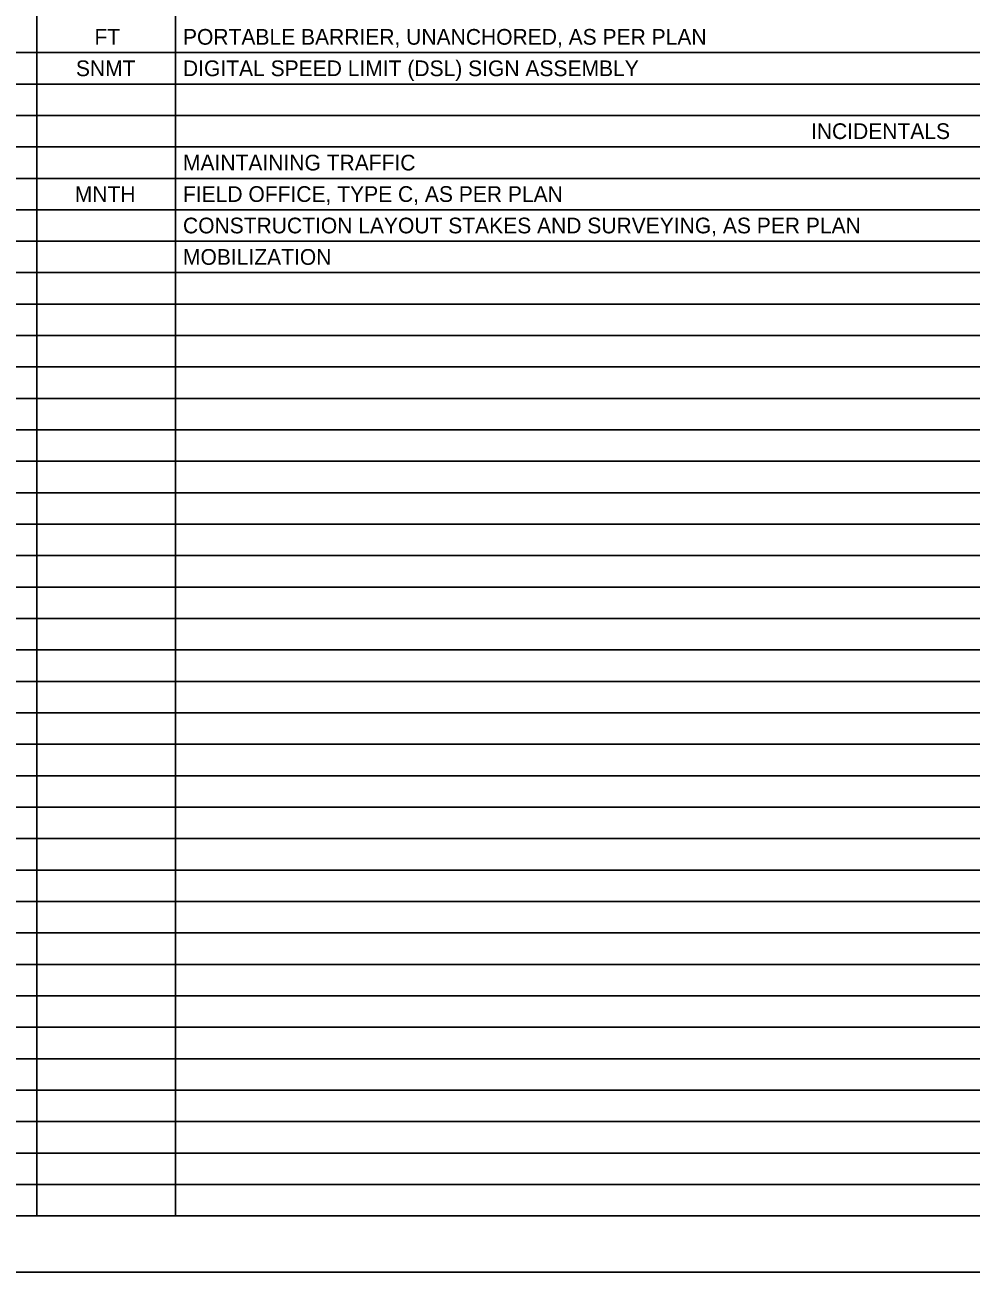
# Model space of a CAD drawing. Extents: x 0 to 34, y 0 to 22.
# Drawn here: x 17.16 to 25.58, y 0 to 11.11 of the extents above; entities that cross this region are included whole.
import ezdxf

# ---------------------------------------------------------------- set-up
doc = ezdxf.new("R2010")
doc.units = 0
for name, color, linetype in [('SH_Border', 7, 'Continuous'), ('SH_Cut_Line', 7, 'Continuous'), ('SH_Data', 7, 'Continuous'), ('SH_Text', 7, 'Continuous')]:
    doc.layers.add(name, color=color, linetype=linetype)

msp = doc.modelspace()

# ---------------------------------------------------------------- linework, layer by layer
at = {"layer": 'SH_Border'}
msp.add_lwpolyline([(1.5, 21.5), (33.5, 21.5), (33.5, 0.5), (1.5, 0.5)], close=True, dxfattribs=at)
at = {"layer": 'SH_Cut_Line'}
msp.add_lwpolyline([(0, 0), (34, 0), (34, 22), (0, 22)], close=True, dxfattribs=at)
at = {"layer": 'SH_Data'}
for p, q in [((17.262, 21.5), (17.262, 0.5)), ((18.498, 21.5), (18.498, 0.5)), ((1.5, 10.86), (32.004, 10.86)), ((1.5, 10.58), (32.004, 10.58)), ((1.5, 10.3), (32.004, 10.3)), ((1.5, 10.02), (32.004, 10.02)), ((1.5, 9.74), (32.004, 9.74)), ((1.5, 9.46), (32.004, 9.46)), ((1.5, 9.18), (32.004, 9.18)), ((1.5, 8.9), (32.004, 8.9)), ((1.5, 8.62), (32.004, 8.62)), ((1.5, 8.34), (32.004, 8.34)), ((1.5, 8.06), (32.004, 8.06)), ((1.5, 7.78), (32.004, 7.78)), ((1.5, 7.5), (32.004, 7.5)), ((1.5, 7.22), (32.004, 7.22)), ((1.5, 6.94), (32.004, 6.94)), ((1.5, 6.66), (32.004, 6.66)), ((1.5, 6.38), (32.004, 6.38)), ((1.5, 6.1), (32.004, 6.1)), ((1.5, 5.82), (32.004, 5.82)), ((1.5, 5.54), (32.004, 5.54)), ((1.5, 5.26), (32.004, 5.26)), ((1.5, 4.98), (32.004, 4.98)), ((1.5, 4.7), (32.004, 4.7)), ((1.5, 4.42), (32.004, 4.42)), ((1.5, 4.14), (32.004, 4.14)), ((1.5, 3.86), (32.004, 3.86)), ((1.5, 3.58), (32.004, 3.58)), ((1.5, 3.3), (32.004, 3.3)), ((1.5, 3.02), (32.004, 3.02)), ((1.5, 2.74), (32.004, 2.74)), ((1.5, 2.46), (32.004, 2.46)), ((1.5, 2.18), (32.004, 2.18)), ((1.5, 1.9), (32.004, 1.9)), ((1.5, 1.62), (32.004, 1.62)), ((1.5, 1.34), (32.004, 1.34)), ((1.5, 1.06), (32.004, 1.06)), ((1.5, 0.78), (32.004, 0.78)), ((1.5, 0.5), (32.004, 0.5))]:
    msp.add_line(p, q, dxfattribs=at)

# ---------------------------------------------------------------- texts
at = {"layer": 'SH_Text'}
for s, p in [('FT', (17.776, 10.93)), ('PORTABLE BARRIER, UNANCHORED, AS PER PLAN', (18.564, 10.93)), ('SNMT', (17.611, 10.65)), ('DIGITAL SPEED LIMIT (DSL) SIGN ASSEMBLY', (18.564, 10.65)), ('INCIDENTALS', (24.154, 10.09)), ('MAINTAINING TRAFFIC', (18.564, 9.81)), ('MNTH', (17.601, 9.53)), ('FIELD OFFICE, TYPE C, AS PER PLAN', (18.564, 9.53)), ('CONSTRUCTION LAYOUT STAKES AND SURVEYING, AS PER PLAN', (18.564, 9.25)), ('MOBILIZATION', (18.564, 8.97))]:
    msp.add_text(s, height=0.14, dxfattribs=at).set_placement(p)

doc.saveas('drawing.dxf')
